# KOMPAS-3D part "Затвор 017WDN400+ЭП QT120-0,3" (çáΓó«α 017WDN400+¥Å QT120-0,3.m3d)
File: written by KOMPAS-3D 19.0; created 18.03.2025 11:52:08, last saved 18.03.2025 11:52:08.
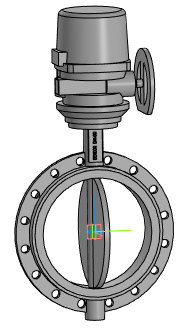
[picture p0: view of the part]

Document properties: Полное имя файла: Затвор 017WDN400+ЭП QT120-0,3.a3d

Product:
- Part/product: Затвор 017WDN400+ЭП QT120-0,3
    Масса: 235.845

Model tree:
1. Операция без истории:1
